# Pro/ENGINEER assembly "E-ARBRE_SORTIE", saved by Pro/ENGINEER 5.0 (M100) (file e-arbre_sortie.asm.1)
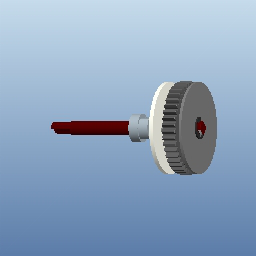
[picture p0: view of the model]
Units: millimeter Newton Second (mmNs); MM, TONNE, HOURS

Other components: 3-AXE_T-S1, 4-BAGUE_ARRET, 13-BAGUE_A-SORTIE, 5-ENTRAINEUR_ROUE, ROUE_Z42-M-1_5, 14-BAGUE_EXT_A-SORTIE, SEGMENT_ARRET_RADIAL_10X1, 7-DISQUE_FREIN

Other named items: A-DROITE, A-DESSUS, A-FACE, A-R0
